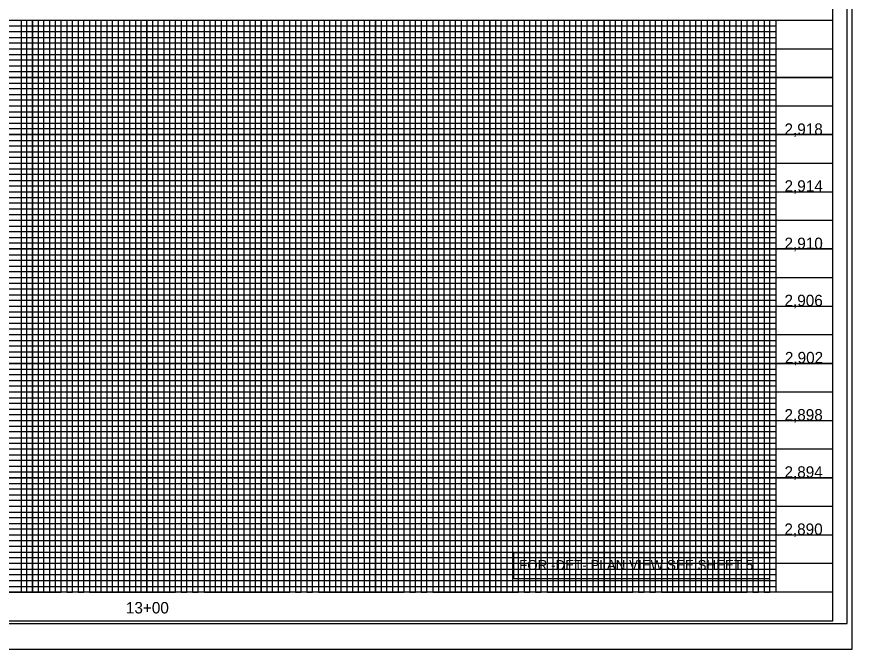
# Model space of a CAD drawing. Extents: x 1191114 to 1192543, y 893004 to 894332.
# Drawn here: x 1191546.9 to 1191839.2, y 893892.3 to 894113.5 of the extents above; entities that cross this region are included whole.
import ezdxf

# ---------------------------------------------------------------- set-up
doc = ezdxf.new("R2010")
doc.units = 0
for name, color, linetype in [('Exist Vertical Profile Ground Line', 7, 'Continuous'), ('Prop Grid Mask', 7, 'Continuous'), ('Prop VPI Label', 7, 'Continuous'), ('Sheet Cutting Line CELL', 7, 'Continuous'), ('Sheet DOT Grid CELL', 7, 'Continuous'), ('Sheet Layout Profile Border Port 2', 7, 'Continuous'), ('Sheet Plot Border Inside CELL', 7, 'Continuous'), ('Sheet Plot Border Outside CELL', 7, 'Continuous'), ('Sheet Profile CELL', 7, 'Continuous'), ('Sheet Profile Grid Major CELL', 7, 'Continuous'), ('Sheet Profile Grid Middle CELL', 7, 'Continuous'), ('Sheet Profile Grid Minor CELL', 7, 'Continuous')]:
    doc.layers.add(name, color=color, linetype=linetype)

msp = doc.modelspace()

# ---------------------------------------------------------------- linework, layer by layer
at = {"layer": 'Prop Grid Mask'}
msp.add_lwpolyline([(1191720.73, 893926.11), (1191810.23, 893926.11), (1191810.23, 893916.95), (1191720.73, 893916.95)], close=True, dxfattribs=at)
at = {"layer": 'Sheet Cutting Line CELL'}
msp.add_line((1191165.59, 893892.3), (1191839.19, 893892.3), dxfattribs=at)
at = {"layer": 'Sheet DOT Grid CELL'}
for p, q in [((1191232.39, 894112.3), (1191832.34, 894112.3)), ((1191552.39, 894112.3), (1191552.39, 893912.3)), ((1191572.39, 894112.3), (1191572.39, 893912.3)), ((1191592.39, 894112.3), (1191592.39, 893912.3)), ((1191612.39, 894112.3), (1191612.39, 893912.3)), ((1191632.39, 894112.3), (1191632.39, 893912.3)), ((1191652.39, 894112.3), (1191652.39, 893912.3)), ((1191672.39, 894112.3), (1191672.39, 893912.3)), ((1191692.39, 894112.3), (1191692.39, 893912.3)), ((1191712.39, 894112.3), (1191712.39, 893912.3)), ((1191732.39, 894112.3), (1191732.39, 893912.3)), ((1191752.39, 894112.3), (1191752.39, 893912.3)), ((1191772.39, 894112.3), (1191772.39, 893912.3)), ((1191792.39, 894112.3), (1191792.39, 893912.3)), ((1191812.39, 894112.3), (1191812.39, 893912.3)), ((1191232.39, 894092.3), (1191832.34, 894092.3)), ((1191232.39, 894072.3), (1191832.34, 894072.3)), ((1191232.39, 894052.3), (1191832.34, 894052.3)), ((1191232.39, 894032.3), (1191832.34, 894032.3)), ((1191232.39, 894012.3), (1191832.34, 894012.3)), ((1191232.39, 893992.3), (1191832.34, 893992.3)), ((1191232.39, 893972.3), (1191832.34, 893972.3)), ((1191232.39, 893952.3), (1191832.34, 893952.3)), ((1191232.39, 893932.3), (1191832.34, 893932.3))]:
    msp.add_line(p, q, dxfattribs=at)
at = {"layer": 'Sheet Layout Profile Border Port 2'}
msp.add_lwpolyline([(1191252.39, 894112.3), (1191812.39, 894112.3), (1191812.39, 893912.3), (1191252.39, 893912.3)], close=True, dxfattribs=at)
at = {"layer": 'Sheet Plot Border Inside CELL'}
msp.add_lwpolyline([(1191170.79, 893901.28), (1191837.39, 893901.28), (1191837.39, 894323.32), (1191170.79, 894323.32)], close=True, dxfattribs=at)
at = {"layer": 'Sheet Plot Border Outside CELL'}
msp.add_lwpolyline([(1191165.59, 893892.3), (1191839.19, 893892.3), (1191839.19, 894332.3), (1191165.59, 894332.3)], close=True, dxfattribs=at)
at = {"layer": 'Sheet Profile CELL'}
for p, q in [((1191232.39, 894112.3), (1191832.39, 894112.3)), ((1191832.39, 893912.3), (1191232.39, 893912.3)), ((1191232.39, 893902.3), (1191832.39, 893902.3))]:
    msp.add_line(p, q, dxfattribs=at)
msp.add_lwpolyline([(1191832.39, 894322.3), (1191232.39, 894322.3), (1191232.39, 893902.3), (1191832.39, 893902.3)], close=True, dxfattribs=at)
at = {"layer": 'Sheet Profile Grid Major CELL'}
for p, q in [((1191552.39, 894112.3), (1191572.39, 894112.3)), ((1191592.39, 894112.3), (1191612.39, 894112.3)), ((1191632.39, 894112.3), (1191652.39, 894112.3)), ((1191672.39, 894112.3), (1191692.39, 894112.3)), ((1191712.39, 894112.3), (1191732.39, 894112.3)), ((1191752.39, 894112.3), (1191772.39, 894112.3)), ((1191792.39, 894112.3), (1191812.39, 894112.3)), ((1191792.39, 893912.3), (1191792.39, 893912.3))]:
    msp.add_line(p, q, dxfattribs=at)
for points in [[(1191532.39, 893912.3), (1191552.39, 893912.3), (1191552.39, 894112.3), (1191572.39, 894112.3), (1191572.39, 893912.3), (1191592.39, 893912.3), (1191592.39, 894112.3), (1191612.39, 894112.3), (1191612.39, 893912.3), (1191632.39, 893912.3), (1191632.39, 894112.3), (1191652.39, 894112.3), (1191652.39, 893912.3), (1191672.39, 893912.3), (1191672.39, 894112.3), (1191692.39, 894112.3), (1191692.39, 893912.3), (1191712.39, 893912.3), (1191712.39, 894112.3), (1191732.39, 894112.3), (1191732.39, 893912.3), (1191752.39, 893912.3), (1191752.39, 894112.3), (1191772.39, 894112.3), (1191772.39, 893912.3), (1191792.39, 893912.3), (1191792.39, 893912.3), (1191792.39, 894112.3), (1191812.39, 894112.3), (1191812.39, 893912.3)], [(1191832.39, 894092.3), (1191232.39, 894092.3)], [(1191832.39, 894072.3), (1191232.39, 894072.3), (1191232.39, 894052.3), (1191832.39, 894052.3)], [(1191832.39, 894032.3), (1191232.39, 894032.3), (1191232.39, 894012.3), (1191832.39, 894012.3)], [(1191832.39, 893992.3), (1191232.39, 893992.3), (1191232.39, 893972.3), (1191832.39, 893972.3)], [(1191832.39, 893952.3), (1191232.39, 893952.3), (1191232.39, 893952.3), (1191232.39, 893932.3), (1191832.39, 893932.3)], [(1191832.39, 893912.3), (1191232.39, 893912.3)]]:
    msp.add_lwpolyline(points, dxfattribs=at)
at = {"layer": 'Sheet Profile Grid Middle CELL'}
for points in [[(1191542.39, 893912.3), (1191562.39, 893912.3), (1191562.39, 894112.3), (1191582.39, 894112.3), (1191582.39, 893912.3), (1191602.39, 893912.3), (1191602.39, 894112.3), (1191622.39, 894112.3), (1191622.39, 893912.3), (1191642.39, 893912.3), (1191642.39, 894112.3), (1191662.39, 894112.3), (1191662.39, 893912.3), (1191682.39, 893912.3), (1191682.39, 894112.3), (1191702.39, 894112.3), (1191702.39, 893912.3), (1191722.39, 893912.3), (1191722.39, 894112.3), (1191742.39, 894112.3), (1191742.39, 893912.3), (1191762.39, 893912.3), (1191762.39, 894112.3), (1191782.39, 894112.3), (1191782.39, 893912.3), (1191802.39, 893912.3), (1191802.39, 894112.3)], [(1191232.39, 894102.3), (1191832.39, 894102.3)], [(1191832.39, 894082.3), (1191232.39, 894082.3), (1191232.39, 894062.3), (1191832.39, 894062.3)], [(1191832.39, 894042.3), (1191232.39, 894042.3), (1191232.39, 894022.3), (1191832.39, 894022.3)], [(1191832.39, 894002.3), (1191232.39, 894002.3), (1191232.39, 893982.3), (1191832.39, 893982.3)], [(1191832.39, 893962.3), (1191232.39, 893962.3), (1191232.39, 893942.3), (1191832.39, 893942.3)], [(1191832.39, 893922.3), (1191232.39, 893922.3)]]:
    msp.add_lwpolyline(points, dxfattribs=at)
at = {"layer": 'Sheet Profile Grid Minor CELL'}
for p, q in [((1191252.39, 894110.3), (1191812.39, 894110.3)), ((1191812.39, 894108.3), (1191252.39, 894108.3)), ((1191252.39, 894106.3), (1191812.39, 894106.3)), ((1191812.39, 894104.3), (1191252.39, 894104.3)), ((1191252.39, 894100.3), (1191812.39, 894100.3)), ((1191812.39, 894098.3), (1191252.39, 894098.3)), ((1191252.39, 894096.3), (1191812.39, 894096.3)), ((1191812.39, 894094.3), (1191252.39, 894094.3)), ((1191252.39, 894090.3), (1191812.39, 894090.3)), ((1191812.39, 894088.3), (1191252.39, 894088.3)), ((1191252.39, 894086.3), (1191812.39, 894086.3)), ((1191812.39, 894084.3), (1191252.39, 894084.3)), ((1191252.39, 894080.3), (1191812.39, 894080.3)), ((1191812.39, 894078.3), (1191252.39, 894078.3)), ((1191252.39, 894076.3), (1191812.39, 894076.3)), ((1191812.39, 894074.3), (1191252.39, 894074.3)), ((1191252.39, 894070.3), (1191812.39, 894070.3)), ((1191812.39, 894068.3), (1191252.39, 894068.3)), ((1191252.39, 894066.3), (1191812.39, 894066.3)), ((1191812.39, 894064.3), (1191252.39, 894064.3)), ((1191252.39, 894060.3), (1191812.39, 894060.3)), ((1191812.39, 894058.3), (1191252.39, 894058.3)), ((1191252.39, 894056.3), (1191812.39, 894056.3)), ((1191812.39, 894054.3), (1191252.39, 894054.3)), ((1191252.39, 894050.3), (1191812.39, 894050.3)), ((1191812.39, 894048.3), (1191252.39, 894048.3)), ((1191252.39, 894046.3), (1191812.39, 894046.3)), ((1191812.39, 894044.3), (1191252.39, 894044.3)), ((1191252.39, 894040.3), (1191812.39, 894040.3)), ((1191812.39, 894038.3), (1191252.39, 894038.3)), ((1191252.39, 894036.3), (1191812.39, 894036.3)), ((1191812.39, 894034.3), (1191252.39, 894034.36)), ((1191252.39, 894030.3), (1191812.39, 894030.3)), ((1191812.39, 894028.3), (1191252.39, 894028.3)), ((1191252.39, 894026.3), (1191812.39, 894026.3)), ((1191812.39, 894024.3), (1191252.39, 894024.3)), ((1191252.39, 894020.3), (1191812.39, 894020.3)), ((1191812.39, 894018.3), (1191252.39, 894018.3)), ((1191252.39, 894016.3), (1191812.39, 894016.3)), ((1191812.39, 894014.3), (1191252.39, 894014.3)), ((1191252.39, 894010.3), (1191812.39, 894010.3)), ((1191812.39, 894008.3), (1191252.39, 894008.3)), ((1191252.39, 894006.3), (1191812.39, 894006.3)), ((1191812.39, 894004.3), (1191252.39, 894004.3)), ((1191252.39, 894000.3), (1191812.39, 894000.3)), ((1191812.39, 893998.3), (1191252.39, 893998.3)), ((1191252.39, 893996.3), (1191812.39, 893996.3)), ((1191812.39, 893994.3), (1191252.39, 893994.3)), ((1191252.39, 893990.3), (1191812.39, 893990.3)), ((1191812.39, 893988.3), (1191252.39, 893988.3)), ((1191252.39, 893986.3), (1191812.39, 893986.3)), ((1191812.39, 893984.3), (1191252.39, 893984.3)), ((1191252.39, 893980.3), (1191812.39, 893980.3)), ((1191812.39, 893978.3), (1191252.39, 893978.3)), ((1191252.39, 893976.3), (1191812.39, 893976.3)), ((1191812.39, 893974.3), (1191252.39, 893974.3)), ((1191252.39, 893970.3), (1191812.39, 893970.3)), ((1191812.39, 893968.3), (1191252.39, 893968.3)), ((1191252.39, 893966.3), (1191812.39, 893966.3)), ((1191812.39, 893964.3), (1191252.39, 893964.3)), ((1191252.39, 893960.3), (1191812.39, 893960.3)), ((1191812.39, 893958.3), (1191252.39, 893958.3)), ((1191252.39, 893956.3), (1191812.39, 893956.3)), ((1191812.39, 893954.3), (1191252.39, 893954.3)), ((1191252.39, 893950.3), (1191812.39, 893950.3)), ((1191812.39, 893948.3), (1191252.39, 893948.3)), ((1191252.39, 893946.3), (1191812.39, 893946.3)), ((1191812.39, 893944.3), (1191252.39, 893944.3)), ((1191252.39, 893940.3), (1191812.39, 893940.3)), ((1191812.39, 893938.3), (1191252.39, 893938.3)), ((1191252.39, 893936.3), (1191812.39, 893936.3)), ((1191812.39, 893934.3), (1191252.39, 893934.3)), ((1191252.39, 893930.3), (1191812.39, 893930.3)), ((1191812.39, 893928.3), (1191252.39, 893928.3)), ((1191252.39, 893926.3), (1191812.39, 893926.3)), ((1191812.39, 893924.3), (1191252.39, 893924.3)), ((1191252.39, 893920.3), (1191812.39, 893920.3)), ((1191812.39, 893918.3), (1191252.39, 893918.3)), ((1191252.39, 893916.3), (1191812.39, 893916.3)), ((1191252.39, 893914.3), (1191812.39, 893914.3)), ((1191812.39, 893914.3), (1191812.39, 893914.3))]:
    msp.add_line(p, q, dxfattribs=at)
for points in [[(1191546.39, 894112.3), (1191548.39, 894112.3), (1191548.39, 893912.3), (1191550.39, 893912.3), (1191550.39, 894112.3), (1191554.39, 894112.3), (1191554.39, 893912.3), (1191556.39, 893912.3), (1191556.39, 894112.3), (1191558.39, 894112.3), (1191558.39, 893912.3), (1191560.39, 893912.3), (1191560.39, 894112.3), (1191564.39, 894112.3), (1191564.39, 893912.3), (1191566.39, 893912.3), (1191566.39, 894112.3), (1191568.39, 894112.3), (1191568.39, 893912.3), (1191570.39, 893912.3), (1191570.39, 894112.3), (1191574.39, 894112.3), (1191574.39, 893912.3), (1191576.27, 893912.52), (1191576.39, 893912.3), (1191576.39, 894112.3), (1191578.39, 894112.3), (1191578.39, 893912.3), (1191580.39, 893912.3), (1191580.39, 894112.3), (1191584.39, 894112.3), (1191584.39, 893912.3), (1191586.39, 893912.3)], [(1191586.39, 893912.3), (1191586.39, 894112.3), (1191588.39, 894112.3), (1191588.39, 893912.3), (1191590.39, 893912.3), (1191590.39, 894112.3), (1191594.39, 894112.3), (1191594.39, 893912.3), (1191596.39, 893912.3), (1191596.39, 894112.3), (1191598.39, 894112.3), (1191598.39, 893912.3), (1191600.39, 893912.3), (1191600.39, 894112.3), (1191604.39, 894112.3), (1191604.39, 893912.3), (1191606.39, 893912.3), (1191606.39, 894112.3), (1191608.39, 894112.3), (1191608.39, 893912.3), (1191610.39, 893912.3), (1191610.39, 894112.3), (1191614.39, 894112.3), (1191614.39, 893912.3), (1191616.39, 893912.3), (1191616.39, 894112.3), (1191618.39, 894112.3), (1191618.39, 893912.3), (1191620.39, 893912.3), (1191620.39, 894112.3), (1191624.39, 894112.3), (1191624.39, 893912.3), (1191626.39, 893912.3), (1191626.39, 894112.3), (1191628.39, 894112.3), (1191628.39, 893912.3), (1191630.39, 893912.3), (1191630.39, 894112.3), (1191634.39, 894112.3), (1191634.39, 893912.3), (1191636.39, 893912.3), (1191636.39, 894112.3), (1191638.39, 894112.3), (1191638.39, 893912.3), (1191640.39, 893912.3), (1191640.39, 894112.3), (1191644.39, 894112.3), (1191644.39, 893912.3), (1191646.39, 893912.3), (1191646.39, 894112.3), (1191648.39, 894112.3), (1191648.39, 893912.3), (1191650.39, 893912.3), (1191650.39, 894112.3), (1191654.39, 894112.3), (1191654.39, 893912.3), (1191656.39, 893912.3), (1191656.39, 894112.3), (1191658.39, 894112.3), (1191658.39, 893912.3), (1191660.39, 893912.3), (1191660.39, 894112.3), (1191664.39, 894112.3), (1191664.39, 893912.3), (1191666.39, 893912.3), (1191666.39, 894112.3), (1191668.39, 894112.3), (1191668.39, 893912.3), (1191670.39, 893912.3), (1191670.39, 894112.3), (1191674.39, 894112.3), (1191674.39, 893912.3), (1191676.39, 893912.3), (1191676.39, 894112.3), (1191678.39, 894112.3), (1191678.39, 893912.3), (1191680.39, 893912.3), (1191680.39, 894112.3), (1191684.39, 894112.3), (1191684.39, 893912.3), (1191686.39, 893912.3), (1191686.39, 894112.3), (1191688.39, 894112.3), (1191688.39, 893912.3), (1191690.39, 893912.3), (1191690.39, 894112.3), (1191694.39, 894112.3), (1191694.39, 893912.3), (1191696.39, 893912.3), (1191696.39, 894112.3), (1191698.39, 894112.3), (1191698.39, 893912.3), (1191700.39, 893912.3), (1191700.39, 894112.3), (1191704.39, 894112.3), (1191704.39, 893912.3), (1191706.39, 893912.3), (1191706.39, 894112.3), (1191708.39, 894112.3), (1191708.39, 893912.3)], [(1191708.39, 893912.3), (1191710.39, 893912.3), (1191710.39, 894112.3), (1191714.39, 894112.3), (1191714.39, 893912.3), (1191716.39, 893912.3), (1191716.39, 894112.3), (1191718.39, 894112.3), (1191718.39, 893912.3), (1191720.39, 893912.3), (1191720.39, 894112.3), (1191724.39, 894112.3), (1191724.39, 893912.3), (1191726.39, 893912.3), (1191726.39, 894112.3), (1191728.39, 894112.3), (1191728.39, 893912.3), (1191730.39, 893912.3), (1191730.39, 894112.3), (1191734.39, 894112.3), (1191734.39, 893912.3), (1191736.39, 893912.3), (1191736.39, 894112.3), (1191738.39, 894112.3), (1191738.39, 893912.3), (1191740.39, 893912.3), (1191740.39, 894112.3), (1191744.39, 894112.3), (1191744.39, 893912.3), (1191746.39, 893912.3), (1191746.39, 894112.3), (1191748.39, 894112.3), (1191748.39, 893912.3), (1191750.39, 893912.3), (1191750.39, 894112.3), (1191754.39, 894112.3), (1191754.39, 893912.3), (1191756.39, 893912.3), (1191756.39, 894112.3), (1191758.39, 894112.3), (1191758.39, 893912.3), (1191760.39, 893912.3), (1191760.39, 894112.3), (1191764.39, 894112.3), (1191764.39, 893912.3), (1191766.39, 893912.3), (1191766.39, 894112.3), (1191768.39, 894112.3), (1191768.39, 893912.3), (1191770.39, 893912.3), (1191770.39, 894112.3), (1191774.39, 894112.3), (1191774.39, 893912.3), (1191776.39, 893912.3), (1191776.39, 894112.3), (1191778.39, 894112.3), (1191778.39, 893912.3), (1191780.39, 893912.3), (1191780.39, 894112.3), (1191784.39, 894112.3), (1191784.39, 893912.3), (1191786.39, 893912.3), (1191786.39, 894112.3), (1191788.39, 894112.3), (1191788.39, 893912.3), (1191790.39, 893912.3), (1191790.39, 894112.3), (1191794.39, 894112.3), (1191794.39, 893912.3), (1191796.39, 893912.3), (1191796.39, 894112.3), (1191798.39, 894112.3), (1191798.39, 893912.3), (1191800.39, 893912.3), (1191800.39, 894112.3), (1191804.39, 894112.3), (1191804.39, 893912.3), (1191806.39, 893912.3), (1191806.39, 894112.3), (1191808.39, 894112.3), (1191808.39, 893912.3), (1191810.39, 893912.3), (1191810.39, 894112.3), (1191812.39, 894112.3)]]:
    msp.add_lwpolyline(points, dxfattribs=at)

# ---------------------------------------------------------------- texts
at = {"layer": 'Exist Vertical Profile Ground Line'}
for s, p in [('2,918', (1191815.48, 894072.2)), ('2,914', (1191815.48, 894052.33)), ('2,910', (1191815.48, 894032.27)), ('2,906', (1191815.48, 894012.3)), ('2,902', (1191815.6, 893992.3)), ('2,898', (1191815.47, 893972.3)), ('2,894', (1191815.47, 893952.3)), ('2,890', (1191815.44, 893932.3)), ('13+00', (1191585.07, 893904.83))]:
    msp.add_text(s, height=4, dxfattribs=at).set_placement(p)
at = {"layer": 'Prop VPI Label'}
msp.add_text('FOR -DET- PLAN VIEW SEE SHEET 5', height=3.5, rotation=360, dxfattribs=at).set_placement((1191722.62, 893920.03))

doc.saveas('drawing.dxf')
